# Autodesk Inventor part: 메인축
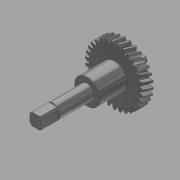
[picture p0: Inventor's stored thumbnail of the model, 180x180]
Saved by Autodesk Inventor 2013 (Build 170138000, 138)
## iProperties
Created: 2017-11
Part Number: 메인축
Material: 강철, 탄소
Document SubType Name: Modeling
Designer: mduedu
Categories: <?xml version="1.0" encoding="UTF-16"?> <MemberInstance><Categories><FamilyTemplate><FamilyTemplateParameter ValueType="xs:double" Id="1" ObjectReferenceKey="da
Density: 7.85 g/cm^3
Mass: 605.821 g
Surface Area: 183.17 cm^2
Volume: 77.1747 cm^3
CustomPartVersion: 1
Author: mduedu
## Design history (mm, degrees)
sketch "Sketch1"
  geometry: C1 r 34.094 at (0, 0)
  constraints: 1 centre point
  dimensions: "d0" = 68.18712 diameter of C1 (= da_da)
extrude "Extrusion1" new body sketch "Sketch1" distance "d1" = 12 (= da_b); taper "d2" = 0 deg
workplane "Work Plane2"
sketch "Sketch2"
  geometry: C1 r 34.094 at (0, 0) reference; C2 r 32.094 at (0, 0)
  constraints: 1 centre point, 1 coincident
  dimensions: "d3" = 64.18712 diameter of C2 (= da_dw)
feature "피치 지름" sketch "Sketch2" dims "d4" = 10, "d5" = 0
workplane "Work Plane8"
workplane "Work Plane9"
feature "스퍼 기어" dims "da_b" = 12, "da_d" = 64.18712, "da_aw" = 54.86964, "da_da" = 68.18712, "da_df" = 59.18712, "da_dw" = 64.18712, angle "da_beta" = 15 deg, "da_lefttooth" = 0, "da_righttooth" = 10
sketch "스케치3"
  geometry: C1 r 15 at (0, 0); 1 further point
  constraints: 1 centre point, 1 coincident
  dimensions: "d49" = 30 diameter of C1
extrude "돌출2" join sketch "스케치3" distance "d50" = 32; taper "d51" = 0 deg
sketch "스케치4"
  geometry: C1 r 8.5 at (0, 0); 1 further point
  constraints: 1 centre point, 1 coincident
  dimensions: "d52" = 17 diameter of C1
extrude "돌출3" join sketch "스케치4" distance "d53" = 60; taper "d54" = 0 deg
sketch "스케치5"
  geometry: C1 r 7.5 at (0, 0); 1 further point
  constraints: 1 centre point, 1 coincident
  dimensions: "d55" = 15 diameter of C1
extrude "돌출4" join sketch "스케치5" distance "d56" = 16; taper "d57" = 0 deg
sketch "스케치6"
  geometry: C1 r 4 at (0, 0); 1 further point
  constraints: 1 centre point, 1 coincident
  dimensions: "d58" = 8 diameter of C1
extrude "돌출5" join sketch "스케치6" distance "d59" = 7; taper "d60" = 0 deg
chamfer "모따기1" distance "d61" = 0.5; stored, may be unused: second distance "d62" = 2, angle "d63" = 45 deg
fillet "모깎기1" dims "d64" = 0.5
sketch "스케치7"
  geometry: L1 (-7, -7)-(7, -7); L2 (7, -7)-(7, 7); L3 (7, 7)-(-7, 7); L4 (-7, 7)-(-7, -7); L5 (-7, -7)-(7, 7); L6 (7, -7)-(-7, 7); L7 (-10, -10)-(10, -10); L8 (10, -10)-(10, 10); L9 (10, 10)-(-10, 10); L10 (-10, 10)-(-10, -10); L11 (-10, -10)-(10, 10); L12 (10, -10)-(-10, 10); 1 further point
  constraints: 24 end point, 4 midpoint, 4 parallel, 2 horizontal, 2 perpendicular
  dimensions: "d65" = 14 distance of L3.end L2.end; "d66" = 14 distance of L2.end L1.end; "d67" = 20 distance of L9.end L8.end; "d68" = 20 distance of L8.end L7.end
extrude "돌출6" cut sketch "스케치7" distance "d69" = 20; taper "d70" = 0 deg
body "Solid1"
body "Srf1"
other parameters: "d16" = 54.86964 (= da_aw), "d17" = 0, "d34" = 1.01342 (computed from da_z), "d39" = 0, "d41" = 0, "d43" = 54.86964 (= da_aw), "d46" = 54.86964 (= da_aw), "d47" = 0, "d48" = 0
